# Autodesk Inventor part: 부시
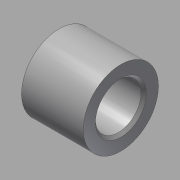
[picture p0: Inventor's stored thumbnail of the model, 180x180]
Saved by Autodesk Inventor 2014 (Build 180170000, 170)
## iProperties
Created: 2016-10
Part Number: 부시
Material: 강철, 연강
Document SubType Name: Modeling
Designer: mduedu
Density: 1 g/cm^3
Appearance: 강철
Author: mduedu
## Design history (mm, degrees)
sketch "스케치1"
  geometry: C1 r 14 at (0, 0); C2 r 8.5 at (0, 0); 1 further point
  constraints: 2 centre point, 2 coincident
  dimensions: "d0" = 28 diameter of C1; "d1" = 17 diameter of C2
extrude "돌출1" new body sketch "스케치1" distance "d2" = 23; taper "d3" = 0 deg
chamfer "모따기1" distance "d4" = 1; stored, may be unused: second distance "d5" = 2, angle "d6" = 45 deg
node "솔리드1"
